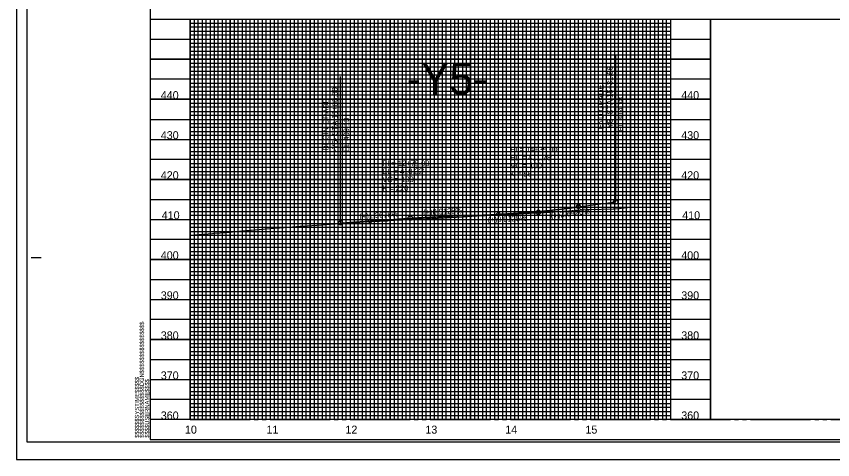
# Model space of a CAD drawing. Extents: x 571503 to 593215, y -77195 to -51828.
# Drawn here: x 582330 to 583349, y -77195 to -76642 of the extents above; entities that cross this region are included whole.
import ezdxf

# ---------------------------------------------------------------- set-up
doc = ezdxf.new("R2010")
doc.units = 0
for name, color, linetype in [('Exist Vertical Profile Ground Line', 7, 'Continuous'), ('Exist Vertical Profile Horizontal Axis Label Major', 7, 'Continuous'), ('Exist Vertical Profile Vertical Axis Label', 7, 'Continuous'), ('Prop PFL Text', 7, 'Continuous'), ('Prop Vertical Profile Curve Label', 7, 'Continuous'), ('Prop Vertical Profile Grade', 7, 'Continuous'), ('Prop Vertical Profile Grade Label', 7, 'Continuous'), ('Prop VPI Label', 7, 'Continuous'), ('Sheet Cutting Line CELL', 7, 'Continuous'), ('Sheet DOT Grid CELL', 7, 'Continuous'), ('Sheet Layout Profile Border Port 2', 7, 'Continuous'), ('Sheet Plot Border Inside CELL', 7, 'Continuous'), ('Sheet Plot Border Outside CELL', 7, 'Continuous'), ('Sheet Profile CELL', 7, 'Continuous'), ('Sheet Profile Grid Major CELL', 7, 'Continuous'), ('Sheet Profile Grid Middle CELL', 7, 'Continuous'), ('Sheet Profile Grid Minor CELL', 7, 'Continuous')]:
    doc.layers.add(name, color=color, linetype=linetype)

msp = doc.modelspace()

# ---------------------------------------------------------------- linework, layer by layer
at = {"layer": 'Exist Vertical Profile Ground Line'}
msp.add_lwpolyline([(582547, -76915), (582575.1, -76912.7), (582577.7, -76912.5), (582591.6, -76911.4), (582591.8, -76911.4), (582621.3, -76908.7), (582623.1, -76908.6), (582623.3, -76908.6), (582638.2, -76907.2), (582640.8, -76907.1), (582670.3, -76904.8), (582670.5, -76904.8), (582684.3, -76903.8), (582686.6, -76903.5), (582686.8, -76903.5), (582687.3, -76903.5), (582716.9, -76901.4), (582718.6, -76901.2), (582721.1, -76901.1), (582722.5, -76901), (582752.2, -76899.1), (582754.2, -76899), (582763.6, -76898.4), (582793.6, -76896.8), (582794.9, -76896.7), (582809.4, -76895.9), (582811.5, -76895.8), (582841.5, -76894.3), (582842.2, -76894.3), (582855.4, -76893.6), (582857, -76893.5), (582887.5, -76891.8), (582888.3, -76891.8), (582903.7, -76890.9), (582905.1, -76890.9), (582926.4, -76889.8), (582935.7, -76889.3), (582936.2, -76889.3), (582946.7, -76888.8), (582948.1, -76888.7), (582978.6, -76887.1), (582979.3, -76887), (582988.1, -76886.6), (582989.8, -76886.5), (583020, -76884.4), (583020.5, -76884.3), (583043.3, -76882.7), (583045.6, -76882.6), (583075.4, -76881.8), (583076.6, -76881.9), (583078, -76881.9), (583083.1, -76881.7), (583085.3, -76881), (583096.8, -76879.9), (583097, -76879.9), (583097.2, -76879.9), (583102.8, -76879.7)], dxfattribs=at)
at = {"layer": 'Prop PFL Text'}
for p, q in [((583078.5, -76873.3), (583078.5, -76690.3)), ((582735, -76899.6), (582735, -76716.5))]:
    msp.add_line(p, q, dxfattribs=at)
at = {"layer": 'Prop Vertical Profile Curve Label'}
for centre in [(583032, -76878.5), (583032, -76879.6), (582872, -76891.3), (582932, -76888.6), (582772, -76897)]:
    msp.add_circle(centre, 2.25, dxfattribs=at)
at = {"layer": 'Prop Vertical Profile Grade'}
for p, q in [((583032, -76879.6), (583078.5, -76873.3)), ((582872, -76891.3), (582932, -76888.6)), ((582735, -76899.6), (582772, -76897))]:
    msp.add_line(p, q, dxfattribs=at)
for points in [[(582932, -76888.6), (582934, -76888.5), (582936, -76888.4), (582938, -76888.3), (582940, -76888.2), (582942, -76888.1), (582944, -76888), (582946, -76887.9), (582948, -76887.8), (582950, -76887.6), (582952, -76887.5), (582954, -76887.4), (582956, -76887.3), (582958, -76887.1), (582960, -76887), (582962, -76886.8), (582964, -76886.7), (582966, -76886.5), (582968, -76886.4), (582970, -76886.2), (582972, -76886.1), (582974, -76885.9), (582976, -76885.7), (582978, -76885.6), (582980, -76885.4), (582982, -76885.2), (582984, -76885), (582986, -76884.8), (582988, -76884.7), (582990, -76884.5), (582992, -76884.3), (582994, -76884.1), (582996, -76883.9), (582998, -76883.7), (583000, -76883.4), (583002, -76883.2), (583004, -76883), (583006, -76882.8), (583008, -76882.6), (583010, -76882.3), (583012, -76882.1), (583014, -76881.9), (583016, -76881.6), (583018, -76881.4), (583020, -76881.1), (583022, -76880.9), (583024, -76880.6), (583026, -76880.4), (583028, -76880.1), (583030, -76879.9), (583032, -76879.6)], [(582772, -76897), (582774, -76896.9), (582776, -76896.8), (582778, -76896.6), (582780, -76896.5), (582782, -76896.4), (582784, -76896.2), (582786, -76896.1), (582788, -76896), (582790, -76895.9), (582792, -76895.7), (582794, -76895.6), (582796, -76895.5), (582798, -76895.3), (582800, -76895.2), (582802, -76895.1), (582804, -76895), (582806, -76894.9), (582808, -76894.7), (582810, -76894.6), (582812, -76894.5), (582814, -76894.4), (582816, -76894.3), (582818, -76894.1), (582820, -76894), (582822, -76893.9), (582824, -76893.8), (582826, -76893.7), (582828, -76893.6), (582830, -76893.5), (582832, -76893.4), (582834, -76893.2), (582836, -76893.1), (582838, -76893), (582840, -76892.9), (582842, -76892.8), (582844, -76892.7), (582846, -76892.6), (582848, -76892.5), (582850, -76892.4), (582852, -76892.3), (582854, -76892.2), (582856, -76892.1), (582858, -76892), (582860, -76891.9), (582862, -76891.8), (582864, -76891.7), (582866, -76891.6), (582868, -76891.5), (582870, -76891.4), (582872, -76891.3)]]:
    msp.add_spline(points, degree=3, dxfattribs=at)
at = {"layer": 'Prop VPI Label'}
for p, q in [((583032, -76879.6), (582984.7, -76886)), ((582932, -76888.6), (582979.2, -76886.5)), ((582772, -76897), (582819.2, -76893.8)), ((582872, -76891.3), (582824.7, -76893.5))]:
    msp.add_line(p, q, dxfattribs=at)
for centre in [(583078.5, -76873.3), (582982, -76886.3), (582735, -76899.6), (582822, -76893.6)]:
    msp.add_circle(centre, 2.75, dxfattribs=at)
at = {"layer": 'Sheet Cutting Line CELL'}
for p, q in [((582330, -76095.2), (582330, -77195.2)), ((582330, -77195.2), (584014, -77195.2))]:
    msp.add_line(p, q, dxfattribs=at)
at = {"layer": 'Sheet DOT Grid CELL'}
for p, q in [((582497, -76645.2), (583996.9, -76645.2)), ((582547, -76645.2), (582547, -77145.2)), ((582597, -76645.2), (582597, -77145.2)), ((582647, -76645.2), (582647, -77145.2)), ((582697, -76645.2), (582697, -77145.2)), ((582747, -76645.2), (582747, -77145.2)), ((582797, -76645.2), (582797, -77145.2)), ((582847, -76645.2), (582847, -77145.2)), ((582897, -76645.2), (582897, -77145.2)), ((582947, -76645.2), (582947, -77145.2)), ((582997, -76645.2), (582997, -77145.2)), ((583047, -76645.2), (583047, -77145.2)), ((583097, -76645.2), (583097, -77145.2)), ((583147, -76645.2), (583147, -77145.2)), ((583197, -76645.2), (583197, -77145.2)), ((582497, -76695.2), (583197, -76695.2)), ((582497, -76745.2), (583197, -76745.2)), ((582497, -76795.2), (583197, -76795.2)), ((582497, -76845.2), (583197, -76845.2)), ((582497, -76895.2), (583197, -76895.2)), ((582497, -76945.2), (583197, -76945.2)), ((582497, -76995.2), (583197, -76995.2)), ((582497, -77045.2), (583197, -77045.2)), ((582497, -77095.2), (583197, -77095.2))]:
    msp.add_line(p, q, dxfattribs=at)
at = {"layer": 'Sheet Layout Profile Border Port 2'}
msp.add_lwpolyline([(582547, -76645.2), (583947, -76645.2), (583947, -77145.2), (582547, -77145.2)], close=True, dxfattribs=at)
at = {"layer": 'Sheet Plot Border Inside CELL'}
msp.add_lwpolyline([(582343, -77172.8), (584009.5, -77172.8), (584009.5, -76117.7), (582343, -76117.7)], close=True, dxfattribs=at)
at = {"layer": 'Sheet Plot Border Outside CELL'}
msp.add_lwpolyline([(582330, -77195.2), (584014, -77195.2), (584014, -76095.2), (582330, -76095.2)], close=True, dxfattribs=at)
at = {"layer": 'Sheet Profile CELL'}
for p, q in [((582497, -76645.2), (583997, -76645.2)), ((582348.5, -76942.7), (582361, -76942.7)), ((583997, -77145.2), (582497, -77145.2)), ((582497, -77170.2), (583997, -77170.2)), ((582497, -77170.2), (582497, -77170.2)), ((582497, -77170.2), (582497, -77170.2)), ((582497, -77170.2), (582497, -77170.2)), ((582497, -77170.2), (582497, -77170.2)), ((582497, -77170.2), (582497, -77170.2)), ((582497, -77170.2), (582497, -77170.2)), ((582497, -77170.2), (582497, -77170.2))]:
    msp.add_line(p, q, dxfattribs=at)
msp.add_lwpolyline([(583997, -76120.2), (582497, -76120.2), (582497, -77170.2), (583997, -77170.2)], close=True, dxfattribs=at)
msp.add_lwpolyline([(582534.5, -77170.2), (582534.5, -77170.2)], dxfattribs=at)
at = {"layer": 'Sheet Profile Grid Major CELL'}
for p, q in [((582547, -76645.2), (582547, -77145.2)), ((582597, -77145.2), (582597, -76645.2)), ((582597, -76645.2), (582647, -76645.2)), ((582647, -76645.2), (582647, -77145.2)), ((582697, -77145.2), (582697, -76645.2)), ((582697, -76645.2), (582747, -76645.2)), ((582747, -76645.2), (582747, -77145.2)), ((582797, -77145.2), (582797, -76645.2)), ((582797, -76645.2), (582847, -76645.2)), ((582847, -76645.2), (582847, -77145.2)), ((582897, -77145.2), (582897, -76645.2)), ((582897, -76645.2), (582947, -76645.2)), ((582947, -76645.2), (582947, -77145.2)), ((582997, -76645.2), (583047, -76645.2)), ((582997, -77145.2), (582997, -76645.2)), ((582997, -76645.2), (583047, -76645.2)), ((583047, -76645.2), (583047, -77145.2)), ((583097, -76645.2), (583147, -76645.2)), ((583097, -77145.2), (583097, -76645.2)), ((583097, -76645.2), (583147, -76645.2)), ((583147, -76645.2), (583147, -77145.2)), ((583197, -76645.2), (583247, -76645.2)), ((583197, -77145.2), (583197, -76645.2)), ((583197, -76645.2), (583247, -76645.2)), ((583297, -76645.2), (583347, -76645.2)), ((583297, -76645.2), (583347, -76645.2)), ((582497, -77145.2), (582497, -77145.2)), ((582547, -77145.2), (582597, -77145.2)), ((582647, -77145.2), (582697, -77145.2)), ((582747, -77145.2), (582797, -77145.2)), ((582847, -77145.2), (582897, -77145.2)), ((582947, -77145.2), (582997, -77145.2)), ((583047, -77145.2), (583097, -77145.2)), ((583147, -77145.2), (583197, -77145.2)), ((583247, -77145.2), (583297, -77145.2)), ((583347, -77145.2), (583397, -77145.2))]:
    msp.add_line(p, q, dxfattribs=at)
for points in [[(583197, -76695.2), (582497, -76695.2)], [(583197, -76745.2), (582497, -76745.2), (582497, -76795.2), (583197, -76795.2)], [(583197, -76845.2), (582497, -76845.2), (582497, -76895.2), (583197, -76895.2)], [(583197, -76945.2), (582497, -76945.2), (582497, -76995.2), (583197, -76995.2)], [(583197, -77045.2), (582497, -77045.2), (582497, -77045.2), (582497, -77095.2), (583197, -77095.2)], [(583997, -77145.2), (582497, -77145.2)]]:
    msp.add_lwpolyline(points, dxfattribs=at)
at = {"layer": 'Sheet Profile Grid Middle CELL'}
for p, q in [((582522, -76645.2), (582572, -76645.2)), ((582572, -76645.2), (582572, -77145.2)), ((582622, -77145.2), (582622, -76645.2)), ((582622, -76645.2), (582672, -76645.2)), ((582672, -76645.2), (582672, -77145.2)), ((582722, -77145.2), (582722, -76645.2)), ((582722, -76645.2), (582772, -76645.2)), ((582772, -76645.2), (582772, -77145.2)), ((582822, -77145.2), (582822, -76645.2)), ((582822, -76645.2), (582872, -76645.2)), ((582872, -76645.2), (582872, -77145.2)), ((582922, -77145.2), (582922, -76645.2)), ((582922, -76645.2), (582972, -76645.2)), ((582972, -76645.2), (582972, -77145.2)), ((583022, -77145.2), (583022, -76645.2)), ((583022, -76645.2), (583072, -76645.2)), ((583072, -76645.2), (583072, -77145.2)), ((583122, -77145.2), (583122, -76645.2)), ((583122, -76645.2), (583172, -76645.2)), ((583222, -76645.2), (583272, -76645.2)), ((583322, -76645.2), (583372, -76645.2)), ((582572, -77145.2), (582622, -77145.2)), ((582672, -77145.2), (582722, -77145.2)), ((582772, -77145.2), (582822, -77145.2)), ((582872, -77145.2), (582922, -77145.2)), ((582972, -77145.2), (583022, -77145.2)), ((583072, -77145.2), (583122, -77145.2)), ((583122, -77145.2), (583122, -77145.2)), ((583172, -77145.2), (583222, -77145.2)), ((583272, -77145.2), (583322, -77145.2))]:
    msp.add_line(p, q, dxfattribs=at)
for points in [[(582497, -76670.2), (583197, -76670.2)], [(583197, -76720.2), (582497, -76720.2), (582497, -76770.2), (583197, -76770.2)], [(583197, -76820.2), (582497, -76820.2), (582497, -76870.2), (583197, -76870.2)], [(583197, -76920.2), (582497, -76920.2), (582497, -76970.2), (583197, -76970.2)], [(583197, -77020.2), (582497, -77020.2), (582497, -77070.2), (583197, -77070.2)], [(583197, -77120.2), (582497, -77120.2)]]:
    msp.add_lwpolyline(points, dxfattribs=at)
at = {"layer": 'Sheet Profile Grid Minor CELL'}
for p, q in [((583077, -76645.2), (583077, -77145.2)), ((583082, -77145.2), (583082, -76645.2)), ((583082, -76645.2), (583087, -76645.2)), ((583087, -76645.2), (583087, -77145.2)), ((583092, -77145.2), (583092, -76645.2)), ((583092, -76645.2), (583102, -76645.2)), ((583102, -76645.2), (583102, -77145.2)), ((583107, -77145.2), (583107, -76645.2)), ((583107, -76645.2), (583112, -76645.2)), ((583112, -76645.2), (583112, -77145.2)), ((583117, -77145.2), (583117, -76645.2)), ((583117, -76645.2), (583127, -76645.2)), ((583127, -76645.2), (583127, -77145.2)), ((583132, -77145.2), (583132, -76645.2)), ((583132, -76645.2), (583137, -76645.2)), ((583137, -76645.2), (583137, -77145.2)), ((583142, -77145.2), (583142, -76645.2)), ((583142, -76645.2), (583152, -76645.2)), ((583157, -76645.2), (583162, -76645.2)), ((583167, -76645.2), (583177, -76645.2)), ((583182, -76645.2), (583187, -76645.2)), ((583192, -76645.2), (583202, -76645.2)), ((583207, -76645.2), (583212, -76645.2)), ((583217, -76645.2), (583227, -76645.2)), ((583232, -76645.2), (583237, -76645.2)), ((583242, -76645.2), (583252, -76645.2)), ((583257, -76645.2), (583262, -76645.2)), ((583267, -76645.2), (583277, -76645.2)), ((583282, -76645.2), (583287, -76645.2)), ((583292, -76645.2), (583302, -76645.2)), ((583307, -76645.2), (583312, -76645.2)), ((583317, -76645.2), (583327, -76645.2)), ((583332, -76645.2), (583337, -76645.2)), ((583342, -76645.2), (583352, -76645.2)), ((582547, -76650.2), (583147, -76650.2)), ((583147, -76655.2), (582547, -76655.2)), ((582547, -76660.2), (583147, -76660.2)), ((583147, -76665.2), (582547, -76665.2)), ((582547, -76675.2), (583147, -76675.2)), ((583147, -76680.2), (582547, -76680.2)), ((582547, -76685.2), (583147, -76685.2)), ((583147, -76690.2), (582547, -76690.2)), ((582547, -76700.2), (583147, -76700.2)), ((583147, -76705.2), (582547, -76705.2)), ((582547, -76710.2), (583147, -76710.2)), ((583147, -76715.2), (582547, -76715.2)), ((582547, -76725.2), (583147, -76725.2)), ((583147, -76730.2), (582547, -76730.2)), ((582547, -76735.2), (583147, -76735.2)), ((583147, -76740.2), (582547, -76740.2)), ((582547, -76750.2), (583147, -76750.2)), ((583147, -76755.2), (582547, -76755.2)), ((582547, -76760.2), (583147, -76760.2)), ((583147, -76765.2), (582547, -76765.2)), ((582547, -76775.2), (583147, -76775.2)), ((583147, -76780.2), (582547, -76780.2)), ((582547, -76785.2), (583147, -76785.2)), ((583147, -76790.2), (582547, -76790.2)), ((582547, -76800.2), (583147, -76800.2)), ((583147, -76805.2), (582547, -76805.2)), ((582547, -76810.2), (583147, -76810.2)), ((583147, -76815.2), (582547, -76815.2)), ((582547, -76825.2), (583147, -76825.2)), ((583147, -76830.2), (582547, -76830.2)), ((582547, -76835.2), (583147, -76835.2)), ((583147, -76840.1), (582547, -76840.1)), ((582547, -76850.2), (583147, -76850.2)), ((583147, -76855.2), (582547, -76855.2)), ((582547, -76860.2), (583147, -76860.2)), ((583147, -76865.2), (582547, -76865.2)), ((582547, -76875.2), (583147, -76875.2)), ((583147, -76880.2), (582547, -76880.2)), ((582547, -76885.2), (583147, -76885.2)), ((583147, -76890.2), (582547, -76890.2)), ((582547, -76900.2), (583147, -76900.2)), ((583147, -76905.2), (582547, -76905.2)), ((582547, -76910.2), (583147, -76910.2)), ((583147, -76915.2), (582547, -76915.2)), ((582547, -76925.2), (583147, -76925.2)), ((583147, -76930.2), (582547, -76930.2)), ((582547, -76935.2), (583147, -76935.2)), ((583147, -76940.2), (582547, -76940.2)), ((582547, -76950.2), (583147, -76950.2)), ((583147, -76955.2), (582547, -76955.2)), ((582547, -76960.2), (583147, -76960.2)), ((583147, -76965.2), (582547, -76965.2)), ((582547, -76975.2), (583147, -76975.2)), ((583147, -76980.2), (582547, -76980.2)), ((582547, -76985.2), (583147, -76985.2)), ((583147, -76990.2), (582547, -76990.2)), ((582547, -77000.2), (583147, -77000.2)), ((583147, -77005.2), (582547, -77005.2)), ((582547, -77010.2), (583147, -77010.2)), ((583147, -77015.2), (582547, -77015.2)), ((582547, -77025.2), (583147, -77025.2)), ((583147, -77030.2), (582547, -77030.2)), ((582547, -77035.2), (583147, -77035.2)), ((583147, -77040.2), (582547, -77040.2)), ((582547, -77050.2), (583147, -77050.2)), ((583147, -77055.2), (582547, -77055.2)), ((582547, -77060.2), (583147, -77060.2)), ((583147, -77065.2), (582547, -77065.2)), ((582547, -77075.2), (583147, -77075.2)), ((583147, -77080.2), (582547, -77080.2)), ((582547, -77085.2), (583147, -77085.2)), ((583147, -77090.2), (582547, -77090.2)), ((582547, -77100.2), (583147, -77100.2)), ((583147, -77105.2), (582547, -77105.2)), ((582547, -77110.2), (583147, -77110.2)), ((583147, -77115.2), (582547, -77115.2)), ((582547, -77125.2), (583147, -77125.2)), ((583147, -77130.2), (582547, -77130.2)), ((582547, -77135.2), (583147, -77135.2)), ((582547, -77140.2), (583147, -77140.2)), ((583077, -77145.2), (583082, -77145.2)), ((583087, -77145.2), (583092, -77145.2)), ((583102, -77145.2), (583107, -77145.2)), ((583112, -77145.2), (583117, -77145.2)), ((583127, -77145.2), (583132, -77145.2)), ((583137, -77145.2), (583142, -77145.2)), ((583152, -77145.2), (583157, -77145.2)), ((583162, -77145.2), (583167, -77145.2)), ((583177, -77145.2), (583182, -77145.2)), ((583187, -77145.2), (583192, -77145.2)), ((583202, -77145.2), (583202, -77145.2)), ((583202, -77145.2), (583207, -77145.2)), ((583212, -77145.2), (583217, -77145.2)), ((583227, -77145.2), (583232, -77145.2)), ((583237, -77145.2), (583242, -77145.2)), ((583252, -77145.2), (583257, -77145.2)), ((583262, -77145.2), (583267, -77145.2)), ((583277, -77145.2), (583282, -77145.2)), ((583287, -77145.2), (583292, -77145.2)), ((583302, -77145.2), (583307, -77145.2)), ((583312, -77145.2), (583317, -77145.2)), ((583327, -77145.2), (583332, -77145.2)), ((583337, -77145.2), (583342, -77145.2))]:
    msp.add_line(p, q, dxfattribs=at)
for points in [[(582547, -76645.2), (582552, -76645.2), (582552, -77145.2), (582557, -77145.2), (582557, -76645.2), (582562, -76645.2), (582562, -77145.2), (582567, -77145.2), (582567, -76645.2), (582577, -76645.2), (582577, -77145.2), (582582, -77145.2), (582582, -76645.2), (582587, -76645.2), (582587, -77145.2), (582592, -77145.2), (582602, -77145.2), (582607, -77145.2), (582607, -76645.2), (582612, -76645.2), (582612, -77145.2), (582617, -77145.2), (582617, -76645.2), (582627, -76645.2), (582627, -77145.2), (582632, -77145.2), (582632, -76645.2), (582637, -76645.2), (582637, -77145.2), (582642, -77145.2), (582642, -76645.2), (582652, -76645.2), (582652, -77145.2), (582657, -77145.2), (582657, -76645.2), (582662, -76645.2), (582662, -77145.2), (582667, -77145.2), (582667, -76645.2), (582677, -76645.2), (582677, -77145.2), (582682, -77145.2), (582682, -76645.2), (582687, -76645.2), (582687, -77145.2), (582692, -77145.2), (582692, -76645.2), (582702, -76645.2), (582702, -77145.2), (582707, -77145.2), (582707, -76645.2), (582712, -76645.2), (582712, -77145.2), (582717, -77145.2), (582717, -76645.2), (582727, -76645.2), (582727, -77145.2), (582732, -77145.2), (582732, -76645.2), (582737, -76645.2), (582737, -77145.2), (582742, -77145.2), (582742, -76645.2), (582752, -76645.2), (582752, -77145.2), (582757, -77145.2), (582757, -76645.2), (582762, -76645.2), (582762, -77145.2)], [(582592, -77145.2), (582592, -76645.2), (582602, -76645.2), (582602, -77145.2)], [(582762, -77145.2), (582767, -77145.2), (582767, -76645.2), (582777, -76645.2), (582777, -77145.2), (582782, -77145.2), (582782, -76645.2), (582787, -76645.2), (582787, -77145.2), (582792, -77145.2), (582792, -76645.2), (582802, -76645.2), (582802, -77145.2), (582807, -77145.2), (582807, -76645.2), (582812, -76645.2), (582812, -77145.2), (582817, -77145.2), (582817, -76645.2), (582827, -76645.2), (582827, -77145.2), (582832, -77145.2), (582832, -76645.2), (582837, -76645.2), (582837, -77145.2), (582842, -77145.2), (582842, -76645.2), (582852, -76645.2), (582852, -77145.2), (582857, -77145.2), (582857, -76645.2), (582862, -76645.2), (582862, -77145.2), (582867, -77145.2), (582867, -76645.2), (582877, -76645.2), (582877, -77145.2), (582882, -77145.2), (582882, -76645.2), (582887, -76645.2), (582887, -77145.2), (582892, -77145.2), (582892, -76645.2), (582902, -76645.2), (582902, -77145.2), (582907, -77145.2), (582907, -76645.2), (582912, -76645.2), (582912, -77145.2), (582917, -77145.2), (582917, -76645.2), (582927, -76645.2), (582927, -77145.2), (582932, -77145.2), (582932, -76645.2), (582937, -76645.2), (582937, -77145.2), (582942, -77145.2), (582942, -76645.2), (582952, -76645.2), (582952, -77145.2), (582957, -77145.2), (582957, -76645.2), (582962, -76645.2), (582962, -77145.2), (582967, -77145.2), (582967, -76645.2), (582977, -76645.2), (582977, -77145.2), (582982, -77145.2), (582982, -76645.2), (582987, -76645.2), (582987, -77145.2), (582992, -77145.2), (582992, -76645.2), (583002, -76645.2), (583002, -77145.2), (583007, -77145.2), (583007, -76645.2), (583012, -76645.2), (583012, -77145.2), (583017, -77145.2), (583017, -76645.2), (583027, -76645.2), (583027, -77145.2), (583032, -77145.2), (583032, -76645.2), (583037, -76645.2), (583037, -77145.2), (583042, -77145.2), (583042, -76645.2), (583052, -76645.2), (583052, -77145.2), (583057, -77145.2), (583057, -76645.2), (583062, -76645.2), (583062, -77145.2), (583067, -77145.2), (583067, -76645.2), (583077, -76645.2)]]:
    msp.add_lwpolyline(points, dxfattribs=at)

# ---------------------------------------------------------------- texts
at = {"layer": 'Exist Vertical Profile Horizontal Axis Label Major'}
for s, p in [('10', (582540.6, -77162.7)), ('11', (582642.4, -77162.7)), ('12', (582741, -77162.7)), ('13', (582840.8, -77162.7)), ('14', (582940.6, -77162.7)), ('15', (583040.7, -77162.7))]:
    msp.add_text(s, height=10, dxfattribs=at).set_placement(p)
at = {"layer": 'Exist Vertical Profile Vertical Axis Label'}
for s, height, p in [('-Y5-', 40, (582817.4, -76739.3)), ('440', 10, (582510.4, -76745)), ('440', 10, (583160.4, -76745)), ('430', 10, (582510.4, -76795)), ('430', 10, (583160.4, -76795)), ('420', 10, (582510.4, -76845)), ('420', 10, (583160.4, -76845)), ('410', 10, (582511.6, -76895)), ('410', 10, (583161.6, -76895)), ('400', 10, (582510.4, -76945)), ('400', 10, (583160.4, -76945)), ('390', 10, (582510.4, -76995)), ('390', 10, (583160.4, -76995)), ('380', 10, (582510.4, -77045)), ('380', 10, (583160.4, -77045)), ('370', 10, (582510.4, -77095)), ('370', 10, (583160.4, -77095)), ('360', 10, (582510.4, -77145)), ('360', 10, (583160.4, -77145))]:
    msp.add_text(s, height=height, dxfattribs=at).set_placement(p)
at = {"layer": 'Prop PFL Text'}
for s, p in [('-Y5- STA 15+31.56', (583074.7, -76784.4)), ('END GRADE', (583063.4, -76782.6)), ('-Y5- STA 11+88.00', (582731.1, -76810.6)), ('BEGIN GRADE', (582719.8, -76808.9)), ('EL 414.38', (583088.2, -76785)), ('EL 409.13', (582745.6, -76810.9))]:
    msp.add_text(s, height=7, rotation=90, dxfattribs=at).set_placement(p)
at = {"layer": 'Prop Vertical Profile Curve Label'}
for s, p in [("VC = 100'", (582947, -76831.3)), ('K = 56', (582946.5, -76841.9)), ("VC = 100'", (582787, -76848.6)), ('K = 220', (582787, -76859.6))]:
    msp.add_text(s, height=7, dxfattribs=at).set_placement(p)
at = {"layer": 'Prop Vertical Profile Grade Label'}
for s, rotation, p in [('(+)1.3678%', 3.9124, (582758.6, -76895)), ('(+)0.9125%', 2.6123, (582838.2, -76889.9)), ('(+)0.9125%', 2.6123, (582918.9, -76899.2)), ('(+)2.6926%', 7.6677, (582998.1, -76894.2))]:
    msp.add_text(s, height=7, rotation=rotation, dxfattribs=at).set_placement(p)
at = {"layer": 'Prop VPI Label'}
for s, p in [('PI = 14+35.00', (582947, -76811.3)), ("EL = 411.78'", (582947, -76821.3)), ('PI = 12+75.00', (582787, -76828.6)), ("EL = 410.32'", (582787, -76838.6))]:
    msp.add_text(s, height=7, dxfattribs=at).set_placement(p)
at = {"layer": 'Sheet Profile CELL'}
for s, p in [('$$$$$$$$$$$$$$$$DGN$$$$$$$$$$$$$$$$', (582489.3, -77167.9)), ('$$$$$$SYSTIME$$$$$', (582483.3, -77167.9)), ('$$$$USERNAME$$$$', (582495.9, -77167.8))]:
    msp.add_text(s, height=5.25, rotation=90, dxfattribs=at).set_placement(p)

doc.saveas('drawing.dxf')
